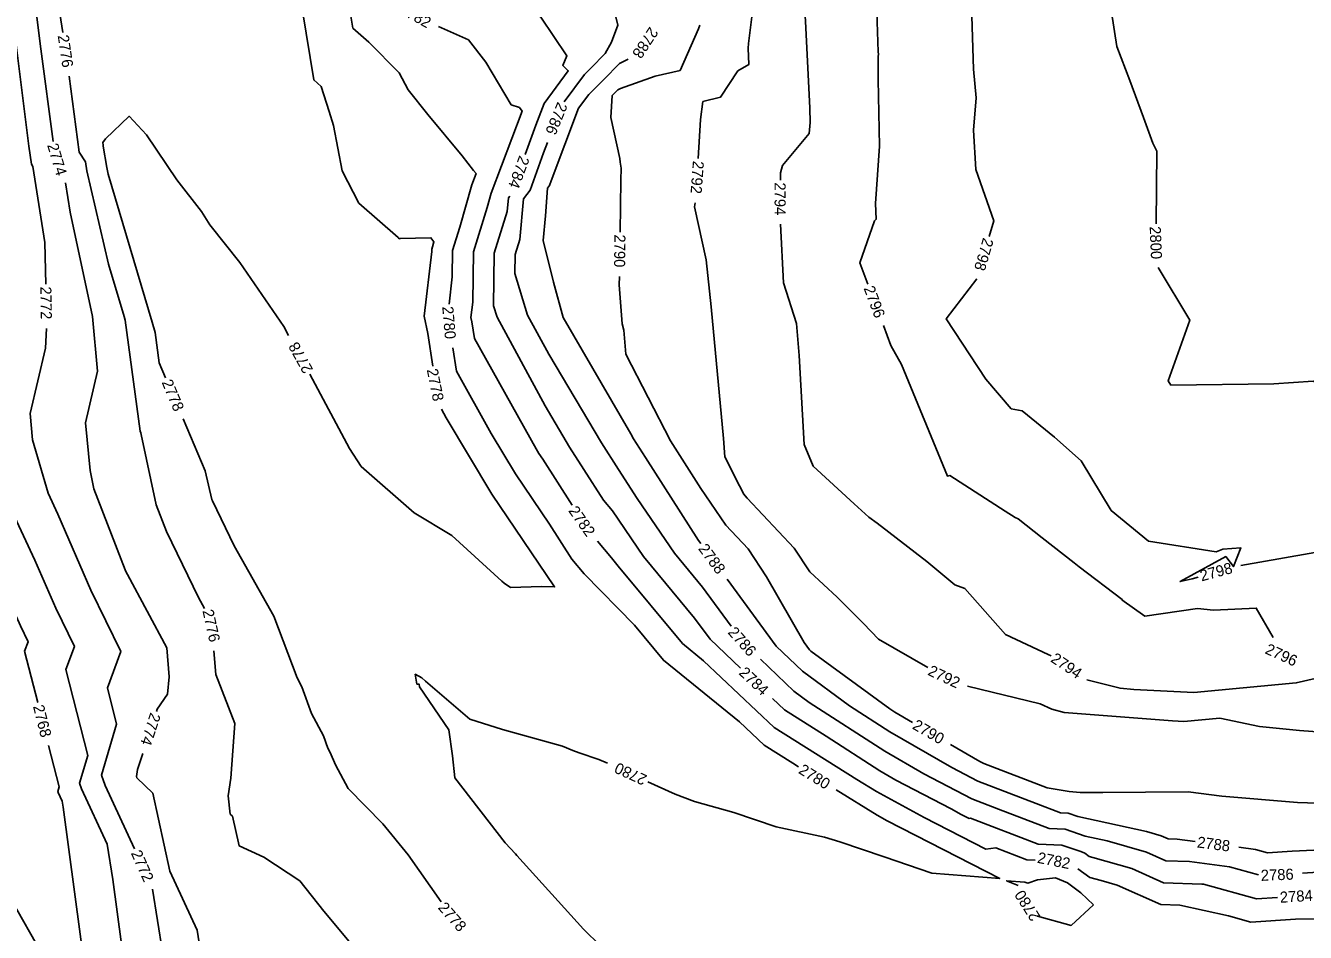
# Model space of a CAD drawing. Extents: x 1326424 to 1329294, y 1001359 to 1003823.
# Drawn here: x 1328279.2 to 1328510.5, y 1001806.2 to 1001970.1 of the extents above; entities that cross this region are included whole.
import ezdxf

# ---------------------------------------------------------------- set-up
doc = ezdxf.new("R2010")
doc.units = 0
doc.layers.add('Prop Rem of Exist Asph Pvmt', color=7, linetype='Continuous')
doc.layers.add('Scratch_Level_3', color=7, linetype='Continuous')

msp = doc.modelspace()

# ---------------------------------------------------------------- linework, layer by layer
at = {"layer": 'Prop Rem of Exist Asph Pvmt'}
for points in [[(1328468.48, 1002031.9), (1328470, 1002020.97), (1328470.41, 1002018.56), (1328470.53, 1002018.07), (1328470.78, 1002017), (1328471.68, 1002006.64), (1328471.55, 1002005.18), (1328471.24, 1002004.51), (1328470.43, 1002002.31), (1328472.5, 1001991.13), (1328472.39, 1001990.72), (1328472.42, 1001990.51), (1328472.41, 1001990.36), (1328474.53, 1001978.76), (1328476.47, 1001966.33), (1328478.82, 1001960.16), (1328481.27, 1001953.45), (1328482.95, 1001948.86), (1328483.71, 1001947.42), (1328483.58, 1001934.24)], [(1328328.64, 1002009.34), (1328328.89, 1002006.73), (1328328.99, 1002003.46), (1328330.54, 1001995.89), (1328331.39, 1001990.9), (1328332.34, 1001988.21), (1328332.65, 1001987.1), (1328335.81, 1001978.47), (1328337.79, 1001973.24), (1328338.38, 1001969.64), (1328341.25, 1001967.09), (1328346.76, 1001961.54), (1328348.41, 1001958.5), (1328351.96, 1001954.02), (1328358.12, 1001946.56), (1328360.18, 1001943.92), (1328360.66, 1001943.33), (1328359.91, 1001941.32), (1328357.72, 1001933.65), (1328356.41, 1001929.44), (1328356.35, 1001924.66), (1328355.77, 1001919.74)], [(1328483.91, 1001926.36), (1328489.64, 1001916.83), (1328485.71, 1001905.86), (1328486.23, 1001905.1), (1328504.83, 1001905.32), (1328511.95, 1001905.81), (1328517.18, 1001903.01), (1328522.69, 1001894.66), (1328524.62, 1001893.84), (1328528.08, 1001891.46), (1328529.55, 1001889.22), (1328531.61, 1001888.19), (1328535.43, 1001888.62), (1328546.11, 1001890.43), (1328546.85, 1001890.73), (1328550.22, 1001891.78), (1328554.56, 1001891.3)], [(1328356.45, 1001911.84), (1328357.1, 1001907.6), (1328363.36, 1001896.39), (1328367.76, 1001889.07), (1328373.91, 1001879.96), (1328377.96, 1001873.62), (1328380.2, 1001870.98), (1328389.27, 1001861.71), (1328394.52, 1001855.39), (1328408.25, 1001844.24), (1328412.69, 1001840.04), (1328417.89, 1001836.77), (1328418.94, 1001836.13)], [(1328384.39, 1001836.75), (1328382.86, 1001837.45), (1328379.28, 1001838.62), (1328378.17, 1001839.06), (1328376.3, 1001839.83), (1328365.43, 1001842.87), (1328359.5, 1001844.75), (1328351.54, 1001851.6), (1328350.85, 1001852.21), (1328349.66, 1001852.84), (1328349.96, 1001851.07), (1328350.39, 1001851.03), (1328350.4, 1001850.6), (1328355.71, 1001842.78), (1328356.42, 1001838.1), (1328356.82, 1001834.15), (1328365.92, 1001822.4), (1328367.8, 1001820.36), (1328367.99, 1001820.09), (1328380.08, 1001806.75), (1328383.13, 1001803.75)], [(1328425.74, 1001831.93), (1328433.15, 1001827.36), (1328434.94, 1001826.38), (1328455.3, 1001815.91), (1328443.04, 1001816.87), (1328434.42, 1001819.86), (1328426.38, 1001822.54), (1328423.61, 1001823.4), (1328414.89, 1001825.29), (1328407.23, 1001827.83), (1328400.12, 1001829.86), (1328396.63, 1001831.15), (1328391.67, 1001833.42)], [(1328472.21, 1001811.14), (1328469.98, 1001813.34), (1328467.54, 1001815.13), (1328465.4, 1001816.04), (1328462.12, 1001815.71), (1328460.39, 1001815.1), (1328459.8, 1001815.24), (1328456.52, 1001815.53), (1328458.6, 1001814.65)], [(1328462.11, 1001809.14), (1328468.21, 1001807.44), (1328472.21, 1001811.14)]]:
    msp.add_lwpolyline(points, dxfattribs=at)
at = {"layer": 'Scratch_Level_3'}
for points in [[(1328273.68, 1002048.34), (1328275.57, 1002032.21), (1328275.17, 1002029.17), (1328275.91, 1002026.39), (1328276.23, 1002023.51), (1328275.86, 1002022), (1328277.89, 1002006.78), (1328278.91, 1001997.2), (1328278.85, 1001991.36), (1328279.7, 1001982.81), (1328280.56, 1001975.97), (1328281.23, 1001972.09), (1328282.01, 1001965.89), (1328284.21, 1001949.16)], [(1328306.32, 1002012.4), (1328303.75, 1002016.51), (1328301.5, 1002023.01), (1328296.08, 1002032.66), (1328285.14, 1002033.54), (1328284.39, 1002033.75), (1328282.38, 1002019.75), (1328281.12, 1002012.11), (1328282.95, 1001994.93), (1328282.93, 1001993.73), (1328284.36, 1001979.33), (1328284.65, 1001977.04), (1328285, 1001975), (1328285.95, 1001968.84)], [(1328350.27, 1002031.26), (1328351.14, 1002011.06), (1328351.26, 1002009.98), (1328355.24, 1001990.86), (1328356.83, 1001987.5), (1328358.78, 1001985.18), (1328361.13, 1001983.68), (1328363.56, 1001983.49), (1328369.6, 1001982.67), (1328374.74, 1001982.78), (1328378.28, 1001981.58), (1328380.34, 1001980.88), (1328380.78, 1001978.75), (1328384.98, 1001975.46), (1328386.3, 1001970.15), (1328385.1, 1001967.11), (1328383.98, 1001965.06), (1328381.39, 1001962.37), (1328380.26, 1001961.27), (1328376.6, 1001956.34)], [(1328426.49, 1002031.76), (1328426.43, 1002031.67), (1328420.24, 1002030.55), (1328419.15, 1002030.04), (1328419.14, 1002029.84), (1328419.44, 1002026.52), (1328424.67, 1002018.16), (1328424.06, 1002008.22), (1328422.51, 1001999.27), (1328420.29, 1001987.79), (1328420.3, 1001987.26), (1328420.32, 1001986.71), (1328422.55, 1001976.83), (1328420.13, 1001971.8), (1328420.17, 1001970.87), (1328420.97, 1001955.15), (1328421.02, 1001952.59), (1328420.88, 1001950.6), (1328416.04, 1001944.81), (1328415.66, 1001943.5), (1328415.65, 1001942.17)], [(1328454.55, 1002030.09), (1328454.56, 1002025.03), (1328455.1, 1002020.57), (1328450.97, 1002005.97), (1328450.25, 1002003.99), (1328450.21, 1002002.75), (1328448.17, 1001995.51), (1328448.45, 1001994.09), (1328448.66, 1001987.42), (1328449.27, 1001983.44), (1328449.17, 1001981.85), (1328450.11, 1001975.7), (1328450.53, 1001962.22), (1328451.03, 1001957.03), (1328450.55, 1001951.19), (1328450.96, 1001944.1), (1328454.21, 1001934.83), (1328453.37, 1001931.99)], [(1328339.71, 1002026.17), (1328340.4, 1002019.29), (1328340.36, 1002009.39), (1328340.85, 1002006.99), (1328347.24, 1001988.85), (1328348.51, 1001984.22), (1328349.85, 1001982.63), (1328355.86, 1001978.78), (1328361.87, 1001975.24), (1328367.28, 1001974.99), (1328369.73, 1001973.46), (1328370.62, 1001973.16), (1328370.66, 1001972.96), (1328372.36, 1001971.63), (1328377.07, 1001964.62), (1328376.32, 1001962.89), (1328377.31, 1001961.92), (1328372.94, 1001956.03), (1328371.47, 1001952.12), (1328369.55, 1001946.78)], [(1328272.39, 1002022.51), (1328272.42, 1002022.11), (1328271.82, 1002019.65), (1328273.68, 1002005.68), (1328274.8, 1001992.42), (1328274.77, 1001988.98), (1328275.04, 1001986.28), (1328276.47, 1001974.9), (1328276.65, 1001973.83), (1328279.85, 1001948.31), (1328280.28, 1001945.05), (1328280.53, 1001944.64), (1328282.71, 1001930.87), (1328282.88, 1001923.35)], [(1328433.03, 1002022.3), (1328433.44, 1002016.16), (1328431.84, 1002000.46), (1328431.82, 1002000.17), (1328431.8, 1002000.06), (1328431.78, 1001999.93), (1328432.14, 1001989.31), (1328432.42, 1001981.9), (1328432.83, 1001979.25), (1328432.9, 1001978.08), (1328433.33, 1001965.36), (1328433.37, 1001964.93), (1328433.33, 1001964.49), (1328433.33, 1001960.37), (1328433.58, 1001948.3), (1328432.86, 1001937.92), (1328432.98, 1001935.1), (1328432.65, 1001934.82), (1328430, 1001927.23), (1328431.46, 1001923.35)], [(1328323.78, 1001996.19), (1328323.78, 1001996.07), (1328325.19, 1001989.23), (1328325.52, 1001987.52), (1328327.88, 1001981.28), (1328331.33, 1001960.26), (1328332.64, 1001959.1), (1328334.09, 1001954.56), (1328334.86, 1001952.05), (1328336.47, 1001943.86), (1328339.44, 1001938.02), (1328346.6, 1001931.76), (1328346.77, 1001931.57), (1328346.92, 1001931.62), (1328352.48, 1001931.73), (1328353.03, 1001931), (1328352.77, 1001930.08), (1328352.64, 1001929.68), (1328352.64, 1001929.23), (1328351.27, 1001917.56), (1328351.91, 1001914.42), (1328352.81, 1001908.52)], [(1328410.56, 1001972.13), (1328409.89, 1001966.86), (1328409.82, 1001966), (1328409.92, 1001963.04), (1328407.97, 1001961.9), (1328404.83, 1001957.18), (1328401.66, 1001956.35), (1328401.21, 1001953.14), (1328400.81, 1001946.04)], [(1328353.86, 1001969.95), (1328359.26, 1001967.51), (1328362.4, 1001963.49), (1328367.02, 1001955.79), (1328368.5, 1001955.27), (1328369.01, 1001954.64), (1328363.4, 1001939.79), (1328362.67, 1001937.22), (1328360.17, 1001929.2), (1328360.05, 1001920.09), (1328359.73, 1001917.31), (1328359.88, 1001916.57), (1328360.34, 1001913.53), (1328371.49, 1001893.57), (1328372, 1001892.74), (1328372.7, 1001891.7), (1328377.99, 1001883.41)], [(1328401.08, 1001970.16), (1328400.87, 1001969.51), (1328397.53, 1001961.97), (1328393.01, 1001960.93), (1328386.77, 1001958.7), (1328386.26, 1001958.45), (1328386.1, 1001958.28), (1328385.23, 1001957.44), (1328384.99, 1001953.48), (1328386.62, 1001946.09), (1328386.67, 1001945.42), (1328386.86, 1001944.32), (1328386.79, 1001942.15), (1328386.67, 1001932.75)], [(1328388.13, 1001964.01), (1328386.57, 1001963.25), (1328383.75, 1001960.33), (1328381.02, 1001957.66), (1328379.18, 1001955.19), (1328374.24, 1001942.02), (1328373.94, 1001941.18), (1328373.54, 1001940.68), (1328373.21, 1001935.73), (1328372.78, 1001931.23), (1328374.63, 1001923.72), (1328376.38, 1001917.33), (1328388.65, 1001896.28), (1328389.12, 1001895.37), (1328391.26, 1001892.01), (1328400.87, 1001877.02), (1328401.26, 1001876.45)], [(1328287.13, 1001960.93), (1328288.93, 1001947.23), (1328290.05, 1001945.45), (1328290.31, 1001943.83), (1328294.25, 1001926.94), (1328297.04, 1001917.48), (1328297.23, 1001916.83), (1328299.96, 1001896.78), (1328300.07, 1001896.51), (1328300.15, 1001896.19), (1328302.84, 1001883.46), (1328304.71, 1001878.62), (1328310.48, 1001866.74), (1328311.56, 1001864.72)], [(1328326.74, 1001914.07), (1328325.93, 1001915.68), (1328317.98, 1001927.28), (1328312.51, 1001934.05), (1328311.04, 1001936.47), (1328306.58, 1001942.19), (1328301.12, 1001950.36), (1328297.98, 1001953.7), (1328293.65, 1001949.64), (1328293.17, 1001948.97), (1328293.24, 1001948.49), (1328293.26, 1001948.32), (1328293.28, 1001948.3), (1328293.9, 1001944.45), (1328294.18, 1001943.23), (1328302.09, 1001916.47), (1328302.63, 1001914.63), (1328303.38, 1001909.15), (1328304.55, 1001906.4)], [(1328373.57, 1001948.97), (1328372.85, 1001947.07), (1328370.42, 1001940.32), (1328369.24, 1001938.8), (1328368.54, 1001931.43), (1328367.69, 1001928.73), (1328367.65, 1001925.31), (1328369.94, 1001917.78), (1328373.79, 1001910.68), (1328383.32, 1001894.65), (1328386.42, 1001889.84), (1328389.78, 1001884.59), (1328396.49, 1001874.71), (1328401.55, 1001868.59), (1328406.75, 1001861.52)], [(1328256.51, 1001943.27), (1328256.62, 1001938.92), (1328258.24, 1001920.25), (1328260.54, 1001907.05), (1328262.68, 1001899.33), (1328268.03, 1001886.16), (1328269.74, 1001880.27), (1328276.76, 1001865.11), (1328278.3, 1001861.57), (1328279.69, 1001858.71), (1328279.07, 1001857.02), (1328281.43, 1001847.71)], [(1328286.46, 1001941.66), (1328287.3, 1001936.36), (1328291.31, 1001917.49), (1328292.26, 1001907.63), (1328290.05, 1001898.29), (1328290.88, 1001889.7), (1328291.59, 1001886.37), (1328297.24, 1001871.73), (1328297.42, 1001871.31), (1328297.63, 1001870.88), (1328304.74, 1001857.61), (1328305.16, 1001852.35), (1328304.91, 1001849.25), (1328303.03, 1001846.56), (1328302.89, 1001846.12)], [(1328366.78, 1001939.28), (1328366.52, 1001938.94), (1328366.28, 1001936.5), (1328363.93, 1001928.97), (1328363.81, 1001919.44), (1328364.44, 1001917.38), (1328373.12, 1001901.34), (1328377.56, 1001893.88), (1328380.13, 1001889.88), (1328383.68, 1001884.31), (1328385.32, 1001882.39), (1328390.92, 1001874.15), (1328400.14, 1001863), (1328402.94, 1001859.19), (1328408.42, 1001853.95)], [(1328400.22, 1001938.06), (1328400.15, 1001937.33), (1328402.24, 1001927.74), (1328403.12, 1001919.23), (1328405.37, 1001895.48), (1328405.62, 1001892.12), (1328408.28, 1001886.91), (1328409.07, 1001885.38), (1328409.29, 1001885.08), (1328409.62, 1001884.68), (1328418.16, 1001875.63), (1328420.98, 1001871.35), (1328425.89, 1001866.8), (1328430.69, 1001862.01), (1328433.39, 1001859.21), (1328442.29, 1001854.08)], [(1328415.65, 1001934.18), (1328416.22, 1001923.61), (1328418.59, 1001916.24), (1328419.04, 1001910.48), (1328419.94, 1001894.35), (1328421.59, 1001890.47), (1328428.97, 1001883.64), (1328431.65, 1001881.21), (1328433.15, 1001880.18), (1328442.11, 1001873.2), (1328447.2, 1001869.02), (1328448.96, 1001868.33), (1328456.36, 1001860.03), (1328464.07, 1001856.4), (1328464.59, 1001856.18)], [(1328386.56, 1001924.75), (1328386.54, 1001923.23), (1328387.07, 1001916.2), (1328387.36, 1001915.06), (1328387.71, 1001910.68), (1328395.78, 1001895.06), (1328401.28, 1001886.43), (1328405.77, 1001879.78), (1328409.81, 1001875.49), (1328413.14, 1001870.43), (1328419.95, 1001858.58), (1328420.9, 1001857.28), (1328421.18, 1001857.02), (1328435.42, 1001846.57), (1328436.35, 1001845.97), (1328439.5, 1001844.15)], [(1328451.13, 1001924.33), (1328445.61, 1001917.1), (1328452.76, 1001906.17), (1328457.38, 1001900.84), (1328459.34, 1001900.45), (1328465.2, 1001895.69), (1328469.99, 1001891.45), (1328475.44, 1001882.46), (1328482.2, 1001876.88), (1328494.38, 1001874.97), (1328495.64, 1001875.45), (1328498.87, 1001875.69), (1328497.52, 1001872.3), (1328496.14, 1001874.1), (1328487.9, 1001869.59), (1328490.05, 1001870.09), (1328491.13, 1001870.41)], [(1328434.28, 1001915.87), (1328435.63, 1001912.27), (1328437.52, 1001908.86), (1328445.85, 1001888.67), (1328446.29, 1001888.75), (1328456.26, 1001882.35), (1328458.1, 1001881.16), (1328458.64, 1001880.96), (1328462.95, 1001877.52), (1328468.75, 1001873.01), (1328469.66, 1001872.29), (1328477.39, 1001866.35), (1328477.44, 1001866.33), (1328477.38, 1001866.3), (1328477.38, 1001866.3), (1328481.49, 1001863.35), (1328491.03, 1001864.75), (1328493.92, 1001864.41), (1328501.65, 1001864.81), (1328504.68, 1001859.5)], [(1328283.01, 1001915.35), (1328282.84, 1001911.78), (1328280.04, 1001899.99), (1328280.51, 1001895.22), (1328283.3, 1001885.59), (1328285.05, 1001881.81), (1328291.05, 1001868.06), (1328296.44, 1001856.97), (1328294.02, 1001850.41), (1328295.68, 1001843.85), (1328292.97, 1001834.63), (1328293.61, 1001832.76), (1328298.92, 1001821.29)], [(1328354.38, 1001900.73), (1328355.23, 1001899.22), (1328363.53, 1001885.41), (1328374.85, 1001868.64), (1328372.5, 1001868.69), (1328366.88, 1001868.52), (1328365.75, 1001869.28), (1328365.3, 1001869.68), (1328356.27, 1001877.94), (1328349.49, 1001882.03), (1328339.91, 1001890.39), (1328337.75, 1001893.62), (1328330.59, 1001907.07)], [(1328307.69, 1001899.04), (1328311.7, 1001889.63), (1328312.9, 1001884.43), (1328312.99, 1001884.22), (1328316.96, 1001876.06), (1328324.09, 1001863.32), (1328328.32, 1001852.17), (1328329.16, 1001850.59), (1328330.91, 1001845.78), (1328333.09, 1001841.73), (1328333.86, 1001839.46), (1328334.31, 1001838.73), (1328335.25, 1001836.5), (1328337.54, 1001832.19), (1328343.81, 1001825.8), (1328348.39, 1001820.21), (1328354.33, 1001811.72)], [(1328498.85, 1001872.5), (1328519.08, 1001876.08), (1328521.42, 1001874.66), (1328523.86, 1001871.84), (1328531.03, 1001867.75), (1328539.31, 1001870.4), (1328548.23, 1001873.74), (1328558.77, 1001878.21), (1328570.15, 1001883.38), (1328574.19, 1001884.07), (1328577.53, 1001885.05), (1328587.12, 1001889.41), (1328591.34, 1001890.81)], [(1328276.83, 1001882.27), (1328280.9, 1001873.46), (1328284.68, 1001864.82), (1328288.06, 1001857.84), (1328286.54, 1001853.71), (1328290.49, 1001838.16), (1328289.01, 1001833.14), (1328289.36, 1001832.13), (1328293.99, 1001822.12), (1328294.99, 1001815.76), (1328298.14, 1001792.36), (1328302.27, 1001789.05)], [(1328382.59, 1001876.88), (1328385.14, 1001873.88), (1328385.34, 1001873.6), (1328386.34, 1001872.38), (1328397.95, 1001858.41), (1328401.78, 1001855.3), (1328414.53, 1001843.23), (1328429.49, 1001833.83), (1328433.01, 1001831.65), (1328441.64, 1001826.95), (1328452.81, 1001821.2), (1328454.57, 1001821.44), (1328460.18, 1001819.29), (1328461.68, 1001819.23)], [(1328406.02, 1001870.02), (1328414.91, 1001857.92), (1328419.63, 1001853.41), (1328428.14, 1001847.16), (1328435.44, 1001842.45), (1328446.65, 1001835.97), (1328451.35, 1001833.52), (1328461.87, 1001829.46), (1328466.28, 1001827.77), (1328467.65, 1001827.71), (1328469.41, 1001827.13), (1328481.82, 1001824.41), (1328484.45, 1001823.65), (1328485.75, 1001823.08), (1328487.33, 1001823.02), (1328490.6, 1001822.6)], [(1328313.27, 1001857.06), (1328313.62, 1001852.83), (1328317.07, 1001843.95), (1328316.34, 1001834.08), (1328315.87, 1001830.84), (1328316.23, 1001827.58), (1328316.64, 1001827.19), (1328317.81, 1001821.84), (1328322.27, 1001819.8), (1328328.78, 1001815.49), (1328333.13, 1001810.02), (1328338.04, 1001804.18), (1328343.58, 1001798.58), (1328348.17, 1001794.02), (1328351.04, 1001793.71), (1328351.9, 1001793.32), (1328356.62, 1001790.11), (1328357.79, 1001789.35), (1328359.75, 1001788.63), (1328368.53, 1001786.5)], [(1328412.05, 1001855.57), (1328418.08, 1001849.8), (1328420.86, 1001847.76), (1328434.53, 1001838.93), (1328441.59, 1001834.85), (1328450.25, 1001830.32), (1328455.1, 1001828.45), (1328464.25, 1001824.94), (1328467.09, 1001824.83), (1328470.73, 1001823.6), (1328474.69, 1001822.74), (1328481.8, 1001820.68), (1328485.31, 1001819.12), (1328489.58, 1001818.97), (1328496.81, 1001818.03), (1328502.08, 1001816.57)], [(1328471.04, 1001851.86), (1328477.04, 1001850.3), (1328479.52, 1001850.11), (1328490.38, 1001849.54), (1328499.31, 1001850.38), (1328508.87, 1001851.27), (1328512.31, 1001852.1), (1328521.05, 1001854.14), (1328527.79, 1001853.6), (1328535.08, 1001852.86), (1328557.28, 1001853.71), (1328558.88, 1001853.38), (1328570.19, 1001854.88)], [(1328414.23, 1001848.45), (1328416.38, 1001846.41), (1328423.95, 1001841.65), (1328433.61, 1001835.41), (1328436.52, 1001833.73), (1328446.5, 1001828.51), (1328448.34, 1001827.51), (1328449.75, 1001826.78), (1328449.98, 1001826.81), (1328462.22, 1001822.12), (1328466.52, 1001821.94), (1328469.97, 1001820.78), (1328470.65, 1001820.49), (1328471.43, 1001819.92), (1328472.14, 1001819.74), (1328479.15, 1001817.71), (1328484.87, 1001815.16), (1328491.83, 1001814.91), (1328492.1, 1001814.88), (1328501.68, 1001812.23), (1328505.5, 1001812.49)], [(1328449.48, 1001850.67), (1328462.61, 1001847.49), (1328464.69, 1001846.51), (1328466.95, 1001845.92), (1328486.51, 1001844.42), (1328488.57, 1001844.31), (1328495.05, 1001844.92), (1328502.25, 1001843.41), (1328509.49, 1001842.65), (1328518.35, 1001842.02), (1328519.42, 1001841.88), (1328525.19, 1001841.35), (1328540.25, 1001839.82), (1328544.26, 1001839.97), (1328546.92, 1001839.43), (1328548.32, 1001839.5)], [(1328283.39, 1001839.96), (1328285.29, 1001832.47), (1328285.05, 1001831.66), (1328285.11, 1001831.49), (1328285.86, 1001829.88), (1328286.02, 1001828.85), (1328291.17, 1001790.59), (1328293.89, 1001788.41), (1328297.6, 1001785.59), (1328303.11, 1001778.78), (1328305, 1001776.92), (1328311.72, 1001773.73), (1328314.62, 1001771.91), (1328317.08, 1001770.55), (1328318.83, 1001769.15), (1328320.08, 1001769.21), (1328327.29, 1001765.79), (1328332.05, 1001763.88)], [(1328446.42, 1001840.15), (1328451.72, 1001837.09), (1328452.44, 1001836.71), (1328463.89, 1001832.3), (1328467.84, 1001831.66), (1328469.85, 1001831.46), (1328473.93, 1001831.48), (1328489.34, 1001831.59), (1328495.45, 1001830.8), (1328509.12, 1001829.66), (1328514.47, 1001829.49), (1328523.49, 1001828.34), (1328529.18, 1001827.81), (1328544.36, 1001829.32)], [(1328300.41, 1001838.52), (1328299.48, 1001835.65), (1328299.29, 1001834.38), (1328299.32, 1001834.15), (1328302.25, 1001831.33), (1328305.32, 1001817.28), (1328310.27, 1001806.6), (1328311.34, 1001799.74), (1328311.5, 1001799.27), (1328318.24, 1001796.47), (1328318.78, 1001790.2), (1328322.6, 1001788.76), (1328323.27, 1001786.74), (1328331.73, 1001788.34), (1328338.88, 1001788.69), (1328343.86, 1001787.54), (1328345.31, 1001786.77), (1328349.82, 1001784.73), (1328351.1, 1001783.85), (1328356.44, 1001780.35), (1328358.88, 1001779.47)], [(1328498.53, 1001821.57), (1328501.52, 1001821.18), (1328503.69, 1001820.58), (1328508.13, 1001820.88), (1328523.8, 1001821.57), (1328527.05, 1001821.87), (1328541.56, 1001823.76), (1328548.21, 1001824.58), (1328561.86, 1001826.48), (1328569.3, 1001828.3), (1328583.85, 1001832.93), (1328587.59, 1001833.87), (1328590.06, 1001834.89), (1328596.36, 1001837.36)], [(1328510.04, 1001816.9), (1328514.68, 1001817.21), (1328522.59, 1001817.56), (1328530.41, 1001818.28), (1328536.27, 1001819.04), (1328551.04, 1001820.86), (1328557.05, 1001821.7), (1328570.41, 1001824.97), (1328576.94, 1001827.05), (1328586.34, 1001829.43), (1328592.56, 1001831.97), (1328599.99, 1001834.89), (1328604.59, 1001836.45), (1328607.05, 1001837.9)], [(1328469.41, 1001817.68), (1328471.57, 1001816.09), (1328473.62, 1001815.57), (1328476.5, 1001814.74), (1328484.43, 1001811.21), (1328487.87, 1001811.08), (1328496.65, 1001809.17), (1328500.67, 1001808.06), (1328508.74, 1001808.59), (1328520.68, 1001808.77), (1328524.69, 1001809.04), (1328535.78, 1001810.74), (1328544.88, 1001811.86), (1328557.88, 1001813.98), (1328566.02, 1001815.98), (1328566.92, 1001816.21)], [(1328302.19, 1001814), (1328303.96, 1001802.67), (1328305.11, 1001794.13), (1328307.1, 1001792.53), (1328307.31, 1001791.93), (1328310.29, 1001788.12), (1328314.27, 1001784.18), (1328318.97, 1001782.33), (1328320.74, 1001781.73), (1328331, 1001782.54), (1328333.42, 1001783), (1328335.01, 1001783.08), (1328336.11, 1001782.82), (1328338.63, 1001781.49), (1328347.35, 1001776.19), (1328352.11, 1001773.04), (1328368.35, 1001766.57), (1328371.16, 1001765.55), (1328373.37, 1001765.02), (1328374.13, 1001764.53), (1328374.6, 1001764.01), (1328375.26, 1001763.6)], [(1328276.4, 1001812.58), (1328282.45, 1001801.85), (1328284.2, 1001788.82), (1328284.94, 1001788.23), (1328291.91, 1001782.94), (1328293.93, 1001780.44), (1328299.06, 1001773.5), (1328304.57, 1001768.05), (1328308.29, 1001765.71), (1328310, 1001764.76), (1328319.51, 1001761.64), (1328330.85, 1001757.09), (1328341.9, 1001749.8), (1328345.06, 1001748.45)]]:
    msp.add_lwpolyline(points, dxfattribs=at)

# ---------------------------------------------------------------- texts
at = {"layer": 'Prop Rem of Exist Asph Pvmt'}
for s, rotation, p in [('2800', 272.4194, (1328482.39, 1001933.78)), ('2780', 274.9288, (1328354.53, 1001919.28)), ('2780', 155.4138, (1328391.7, 1001834.5)), ('2780', 328.3257, (1328418.77, 1001835.06)), ('2780', 122.517, (1328462.73, 1001809.04))]:
    msp.add_text(s, height=2, rotation=rotation, dxfattribs=at).set_placement(p)
at = {"layer": 'Scratch_Level_3'}
for s, rotation, p in [('2782', 330.379, (1328346.61, 1001972.5)), ('2788', 236.463, (1328392.06, 1001970)), ('2776', 278.5253, (1328285.03, 1001968.28)), ('2786', 247.6081, (1328375.41, 1001956.41)), ('2774', 286.7097, (1328283.12, 1001948.48)), ('2784', 249.7452, (1328368.5, 1001946.72)), ('2792', 265.7632, (1328399.85, 1001945.69)), ('2794', 270.0445, (1328414.6, 1001941.75)), ('2790', 269.2612, (1328385.66, 1001932.35)), ('2798', 253.7262, (1328452.31, 1001931.86)), ('2772', 270.9342, (1328281.9, 1001922.92)), ('2796', 290.641, (1328430.67, 1001922.61)), ('2778', 118.8143, (1328331.26, 1001907.91)), ('2778', 281.4083, (1328351.73, 1001907.88)), ('2778', 293.0875, (1328303.79, 1001905.63)), ('2782', 305.2172, (1328377.26, 1001882.38)), ('2788', 306.515, (1328400.72, 1001875.53)), ('2798', 15.147, (1328491.78, 1001869.62)), ('2776', 282.5773, (1328311.19, 1001864.32)), ('2786', 311.6947, (1328406.03, 1001860.34)), ('2796', 335.5595, (1328503.09, 1001856.67)), ('2794', 326.1685, (1328464.35, 1001855.22)), ('2784', 316.5361, (1328408.03, 1001852.94)), ('2792', 334.6499, (1328442.13, 1001852.79)), ('2768', 284.2213, (1328280.56, 1001847.05)), ('2774', 251.9338, (1328301.81, 1001846.04)), ('2790', 329.9972, (1328439.36, 1001843.08)), ('2788', 352.6245, (1328490.88, 1001821.55)), ('2772', 294.1185, (1328298.23, 1001820.52)), ('2782', 348.708, (1328461.97, 1001818.78)), ('2786', 2.3287, (1328502.51, 1001815.49)), ('2784', 3.8181, (1328505.98, 1001811.52)), ('2778', 311.2659, (1328353.66, 1001810.59))]:
    msp.add_text(s, height=2, rotation=rotation, dxfattribs=at).set_placement(p)

doc.saveas('drawing.dxf')
